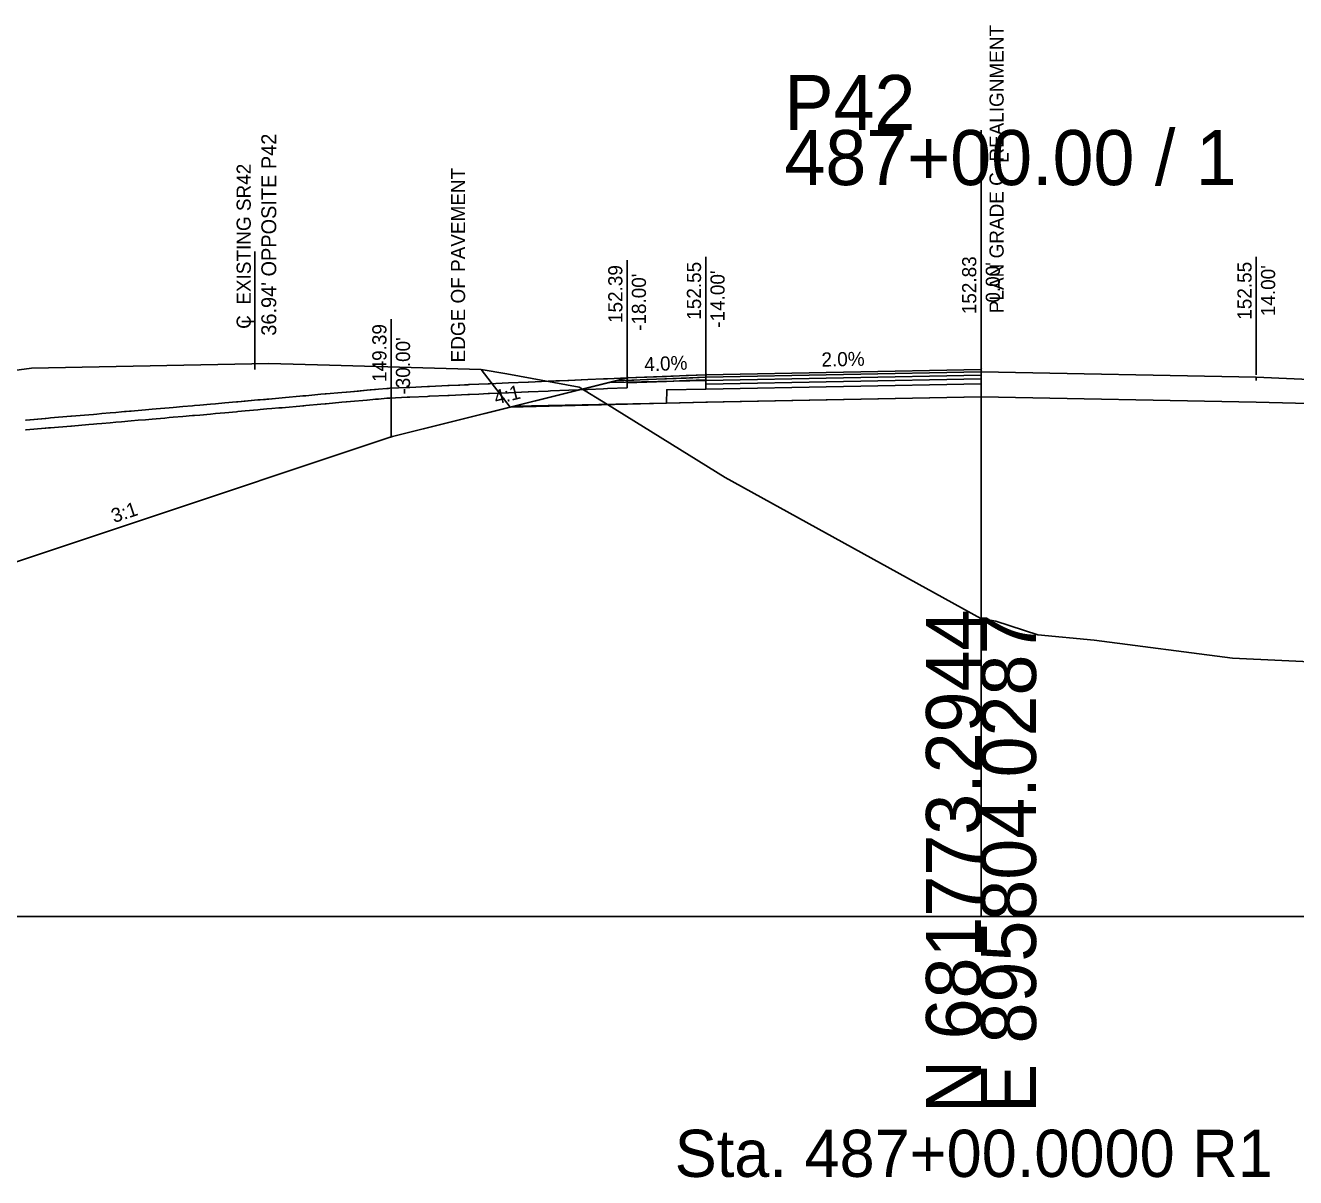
# Model space of a CAD drawing. Extents: x -100 to 7529, y -13 to 10775.
# Drawn here: x 3101.4 to 3166, y 5486.7 to 5545.3 of the extents above; entities that cross this region are included whole.
import ezdxf

# ---------------------------------------------------------------- set-up
doc = ezdxf.new("R2010")
doc.units = 0
for name, color, linetype in [('ASHPALT_12_5MM1', 7, 'Continuous'), ('ASPHALT_19MM1', 7, 'Continuous'), ('ASPHALT_19MM2', 7, 'Continuous'), ('ASPHALT_9_5MM1', 7, 'Continuous'), ('CONST_LV3', 7, 'Continuous'), ('CONST_PROF_LV1', 7, 'Continuous'), ('Default', 7, 'Continuous'), ('Draft_XS_Text', 7, 'Continuous'), ('DTM CONTOURS_MAJOR', 7, 'Continuous'), ('DTM_P_FINISHED_GRADE', 7, 'Continuous'), ('DTM_X_BOUNDARY', 7, 'Continuous'), ('DTM_X_GROUND', 7, 'Continuous'), ('XS_CELL', 7, 'Continuous'), ('XS_M_SHAPES_EARTHWORK', 7, 'Continuous'), ('XS_P_CRUSHED_STONE', 7, 'Continuous'), ('XS_P_DR_ASPHALT', 7, 'Continuous'), ('XS_P_DR_ASPHALT_B', 7, 'Continuous'), ('XS_P_DR_GRAVEL', 7, 'Continuous'), ('XS_P_GROUND', 7, 'Continuous'), ('XS_P_SHOULDER', 7, 'Continuous'), ('XS_P_SUBGRADE_GRANULAR', 7, 'Continuous'), ('XS_P_TX_CLEARZONE', 7, 'Continuous'), ('XS_P_TX_FS_BS', 7, 'Continuous')]:
    doc.layers.add(name, color=color, linetype=linetype)

msp = doc.modelspace()

# ---------------------------------------------------------------- linework, layer by layer
at = {"layer": 'ASHPALT_12_5MM1'}
msp.add_line((3164, 5527.257), (3164, 5527.424), dxfattribs=at)
at = {"layer": 'ASPHALT_19MM1'}
msp.add_lwpolyline([(3136, 5527.257), (3150, 5527.537), (3150, 5527.349), (3150, 5527.349), (3136, 5527.069), (3136, 5527.069), (3136, 5527.069), (3136, 5527.257), (3136, 5527.257)], dxfattribs=at)
at = {"layer": 'ASPHALT_19MM2'}
msp.add_lwpolyline([(3136, 5527.069), (3150, 5527.349), (3150, 5527.099), (3150, 5527.099), (3136, 5526.819), (3136, 5526.819), (3136, 5526.819), (3136, 5527.069), (3136, 5527.069)], dxfattribs=at)
at = {"layer": 'ASPHALT_9_5MM1'}
msp.add_lwpolyline([(3136, 5527.549), (3150, 5527.829), (3150, 5527.704), (3150, 5527.704), (3136, 5527.424), (3136, 5527.424), (3136, 5527.424), (3136, 5527.549), (3136, 5527.549)], dxfattribs=at)
at = {"layer": 'CONST_LV3'}
for points in [[(3101.397, 5525.247), (3101.435, 5525.25), (3101.438, 5525.251), (3102.44, 5525.334), (3102.575, 5525.346), (3102.665, 5525.354), (3103.714, 5525.442), (3103.747, 5525.445), (3104.63, 5525.518), (3104.853, 5525.539), (3105.026, 5525.554), (3105.29, 5525.576), (3105.7, 5525.61), (3105.992, 5525.637), (3106.278, 5525.661), (3106.445, 5525.677), (3106.945, 5525.719), (3107.13, 5525.736), (3107.507, 5525.767), (3107.843, 5525.795), (3108.267, 5525.835), (3108.713, 5525.872), (3108.917, 5525.889), (3109.402, 5525.935), (3109.897, 5525.976), (3109.991, 5525.984), (3110.263, 5526.006), (3110.807, 5526.057), (3111.062, 5526.078), (3111.066, 5526.079), (3111.546, 5526.118), (3112.14, 5526.174), (3112.209, 5526.18), (3112.527, 5526.21), (3112.886, 5526.239), (3113.215, 5526.27), (3113.339, 5526.28), (3113.6, 5526.302), (3114.288, 5526.366), (3114.453, 5526.379), (3114.63, 5526.394), (3115.36, 5526.462), (3115.513, 5526.474), (3115.553, 5526.478), (3115.66, 5526.486), (3116.431, 5526.558), (3116.639, 5526.575), (3116.692, 5526.579), (3117.499, 5526.654), (3117.713, 5526.671), (3117.724, 5526.672), (3118.138, 5526.71), (3118.338, 5526.726), (3118.756, 5526.765), (3118.776, 5526.767), (3118.935, 5526.779), (3119.787, 5526.858), (3119.829, 5526.861), (3119.864, 5526.862), (3119.938, 5526.866), (3120.819, 5526.907), (3120.873, 5526.91), (3120.942, 5526.912), (3121.848, 5526.955), (3121.908, 5526.957), (3121.948, 5526.959), (3122.877, 5527.002), (3122.936, 5527.004), (3122.955, 5527.005), (3123.425, 5527.026), (3123.487, 5527.029), (3123.958, 5527.05), (3123.963, 5527.05), (3123.979, 5527.051), (3124.94, 5527.094), (3125.001, 5527.097), (3125.971, 5527.139), (3126.963, 5527.182), (3126.988, 5527.183), (3127.984, 5527.225), (3128.381, 5527.242), (3128.989, 5527.267), (3128.995, 5527.267), (3129.998, 5527.308), (3130.791, 5527.34), (3131, 5527.349), (3132, 5527.389), (3133, 5527.429), (3134, 5527.469), (3135, 5527.509), (3136, 5527.549)], [(3120, 5524.389), (3120, 5524.389), (3126.28, 5525.958)]]:
    msp.add_lwpolyline(points, dxfattribs=at)
at = {"layer": 'Default'}
msp.add_lwpolyline([(3136, 5527.424), (3150, 5527.704), (3150, 5527.537), (3150, 5527.537), (3136, 5527.257), (3136, 5527.257), (3136, 5527.257), (3136, 5527.424), (3136, 5527.424)], dxfattribs=at)
at = {"layer": 'DTM_P_FINISHED_GRADE'}
for points in [[(3132, 5527.389), (3133, 5527.429), (3134, 5527.469), (3135, 5527.509), (3136, 5527.549)], [(3101.397, 5525.247), (3101.435, 5525.25), (3101.437, 5525.25), (3102.404, 5525.331), (3102.44, 5525.334), (3102.575, 5525.346), (3102.665, 5525.354), (3103.714, 5525.442), (3103.747, 5525.445), (3104.63, 5525.518), (3104.853, 5525.539), (3105.026, 5525.554), (3105.29, 5525.576), (3105.7, 5525.61), (3105.992, 5525.637), (3106.278, 5525.661), (3106.771, 5525.702), (3107.13, 5525.736), (3107.507, 5525.767), (3107.843, 5525.795), (3108.049, 5525.815), (3108.49, 5525.851), (3108.713, 5525.872), (3108.917, 5525.889), (3109.402, 5525.935), (3109.897, 5525.976), (3109.991, 5525.984), (3110.263, 5526.006), (3110.807, 5526.057), (3111.062, 5526.078), (3111.066, 5526.079), (3111.546, 5526.118), (3112.14, 5526.174), (3112.209, 5526.18), (3112.572, 5526.21), (3113.215, 5526.27), (3113.339, 5526.28), (3113.68, 5526.312), (3113.937, 5526.333), (3114.288, 5526.366), (3114.453, 5526.379), (3114.63, 5526.394), (3115.36, 5526.462), (3115.513, 5526.474), (3115.553, 5526.478), (3115.66, 5526.486), (3116.431, 5526.558), (3116.639, 5526.575), (3116.692, 5526.579), (3117.499, 5526.654), (3117.713, 5526.671), (3117.724, 5526.672), (3117.934, 5526.689), (3118.756, 5526.765), (3118.776, 5526.767), (3119.206, 5526.806), (3119.355, 5526.818), (3119.787, 5526.858), (3119.829, 5526.861), (3119.864, 5526.862), (3119.938, 5526.866), (3120.819, 5526.907), (3120.873, 5526.91), (3120.942, 5526.912), (3121.849, 5526.955), (3121.908, 5526.957), (3121.948, 5526.959), (3122.877, 5527.002), (3122.936, 5527.004), (3122.955, 5527.005), (3123.903, 5527.048), (3123.958, 5527.05), (3123.963, 5527.05), (3123.979, 5527.051), (3124.455, 5527.072), (3124.94, 5527.094), (3125.001, 5527.097), (3125.971, 5527.139), (3126.963, 5527.182), (3126.988, 5527.183), (3127.984, 5527.225), (3128.103, 5527.232), (3129.032, 5527.269), (3130.004, 5527.309), (3130.011, 5527.309), (3130.791, 5527.34), (3131, 5527.349), (3132, 5527.389)]]:
    msp.add_lwpolyline(points, dxfattribs=at)
at = {"layer": 'DTM_X_GROUND'}
for p, q in [((3126.052, 5525.901), (3124.572, 5527.826)), ((3136, 5527.424), (3131.405, 5527.24)), ((3136, 5527.424), (3150, 5527.704)), ((3150, 5527.704), (3164, 5527.424)), ((3164, 5527.424), (3168.595, 5527.24))]:
    msp.add_line(p, q, dxfattribs=at)
for points in [[(3000, 5512.2), (3044.132, 5513.453), (3046.486, 5513.62), (3053.808, 5513.95), (3070.909, 5514.966), (3077.153, 5518.209), (3097.118, 5527.209), (3098.789, 5527.5), (3101.713, 5527.882), (3110.312, 5528.066), (3113.777, 5528.123), (3116.864, 5528.039), (3124.572, 5527.826)], [(3126.052, 5525.901), (3131.405, 5527.24)]]:
    msp.add_lwpolyline(points, dxfattribs=at)
at = {"layer": 'XS_CELL'}
for p, q in [((3150, 5500), (3150, 5540)), ((3150, 5500), (3150, 5540)), ((3000, 5500), (3150, 5500)), ((3000, 5500), (3150, 5500)), ((3150, 5500), (3300, 5500)), ((3150, 5500), (3300, 5500))]:
    msp.add_line(p, q, dxfattribs=at)
at = {"layer": 'XS_M_SHAPES_EARTHWORK'}
for points in [[(3070.973, 5514.999), (3077.153, 5518.209), (3097.118, 5527.209), (3098.789, 5527.5), (3101.713, 5527.882), (3110.312, 5528.066), (3113.777, 5528.123), (3116.864, 5528.039), (3124.572, 5527.826), (3125.877, 5527.605), (3129.562, 5526.928), (3131.005, 5526.033), (3126.052, 5525.901), (3120, 5524.389), (3093.161, 5515.443)], [(3131.005, 5526.033), (3136.992, 5522.323), (3149.998, 5515.154), (3150, 5515.153), (3150.751, 5515.018), (3152.885, 5514.328), (3155.752, 5514.055), (3162.783, 5513.146), (3170.679, 5512.757), (3221.28, 5511.155), (3220.912, 5511.208), (3220.685, 5511.235), (3219.104, 5511.457), (3219.093, 5511.459), (3219.08, 5511.46), (3218.589, 5511.527), (3180, 5524.389), (3174.059, 5525.874), (3166, 5526.113), (3165.996, 5526.113), (3164, 5526.153), (3150, 5526.433), (3136, 5526.153), (3134, 5526.113)]]:
    msp.add_lwpolyline(points, close=True, dxfattribs=at)
at = {"layer": 'XS_P_CRUSHED_STONE'}
for points in [[(3132, 5527.389), (3132, 5527.389), (3131.106, 5527.165), (3131.106, 5527.165), (3131.106, 5527.165), (3136, 5527.257), (3136, 5527.257), (3136, 5527.549), (3132, 5527.389)], [(3134, 5526.113), (3136.078, 5526.154), (3136.078, 5526.154), (3150, 5526.433), (3150, 5526.433), (3150, 5527.099), (3136, 5526.819), (3136, 5526.819), (3134.014, 5526.792), (3134.014, 5526.792), (3134, 5526.113), (3134, 5526.113), (3134, 5526.113)]]:
    msp.add_lwpolyline(points, dxfattribs=at)
at = {"layer": 'XS_P_DR_ASPHALT'}
msp.add_lwpolyline([(3132, 5527.389), (3132, 5527.264), (3133, 5527.304), (3133, 5527.304), (3133, 5527.304), (3133, 5527.304), (3134, 5527.344), (3134, 5527.344), (3134, 5527.344), (3134, 5527.344), (3135, 5527.384), (3135, 5527.384), (3135, 5527.384), (3136, 5527.424), (3136, 5527.549), (3135, 5527.509), (3135, 5527.509), (3135, 5527.509), (3134, 5527.469), (3134, 5527.469), (3134, 5527.469), (3134, 5527.469), (3133, 5527.429), (3133, 5527.429), (3133, 5527.429), (3133, 5527.429), (3132, 5527.389)], dxfattribs=at)
at = {"layer": 'XS_P_DR_ASPHALT_B'}
msp.add_lwpolyline([(3132, 5527.264), (3132, 5527.139), (3133, 5527.179), (3133, 5527.179), (3133, 5527.179), (3133, 5527.179), (3134, 5527.219), (3134, 5527.219), (3134, 5527.219), (3134, 5527.219), (3135, 5527.259), (3135, 5527.259), (3135, 5527.259), (3136, 5527.299), (3136, 5527.424), (3135, 5527.384), (3135, 5527.384), (3135, 5527.384), (3134, 5527.344), (3134, 5527.344), (3134, 5527.344), (3134, 5527.344), (3133, 5527.304), (3133, 5527.304), (3133, 5527.304), (3133, 5527.304), (3132, 5527.264)], dxfattribs=at)
at = {"layer": 'XS_P_DR_GRAVEL'}
for points in [[(3101.435, 5525.25), (3101.437, 5525.25), (3102.404, 5525.331), (3102.44, 5525.334), (3102.575, 5525.346), (3102.665, 5525.354), (3103.714, 5525.442), (3103.747, 5525.445), (3104.63, 5525.518), (3104.853, 5525.539), (3105.026, 5525.554), (3105.29, 5525.576), (3105.7, 5525.61), (3105.992, 5525.637), (3106.278, 5525.661), (3106.771, 5525.702), (3107.13, 5525.736), (3107.507, 5525.767), (3107.843, 5525.795), (3108.049, 5525.815), (3108.49, 5525.851), (3108.713, 5525.872), (3108.917, 5525.889), (3109.402, 5525.935), (3109.897, 5525.976), (3109.991, 5525.984), (3110.263, 5526.006), (3110.807, 5526.057), (3111.062, 5526.078), (3111.066, 5526.079), (3111.546, 5526.118), (3112.14, 5526.174), (3112.209, 5526.18), (3112.572, 5526.21), (3113.215, 5526.27), (3113.339, 5526.28), (3113.68, 5526.312), (3113.937, 5526.333), (3114.288, 5526.366), (3114.453, 5526.379), (3114.63, 5526.394), (3115.36, 5526.462), (3115.513, 5526.474), (3115.553, 5526.478), (3115.66, 5526.486), (3116.431, 5526.558), (3116.639, 5526.575), (3116.692, 5526.579), (3117.499, 5526.654), (3117.713, 5526.671), (3117.724, 5526.672), (3117.934, 5526.689), (3118.756, 5526.765), (3118.776, 5526.767), (3119.206, 5526.806), (3119.355, 5526.818), (3119.787, 5526.858), (3119.829, 5526.861), (3119.864, 5526.862), (3119.938, 5526.866), (3120.819, 5526.907), (3120.873, 5526.91), (3120.942, 5526.912), (3121.849, 5526.955), (3121.908, 5526.957), (3121.948, 5526.959), (3122.877, 5527.002), (3122.936, 5527.004), (3122.955, 5527.005), (3123.903, 5527.048), (3123.958, 5527.05), (3123.963, 5527.05), (3123.979, 5527.051), (3124.455, 5527.072), (3124.94, 5527.094), (3125.001, 5527.097), (3125.971, 5527.139), (3126.963, 5527.182), (3126.988, 5527.183), (3127.984, 5527.225), (3128.103, 5527.232), (3129.032, 5527.269), (3130.004, 5527.309), (3130.011, 5527.309), (3130.791, 5527.34), (3131, 5527.349), (3131, 5527.349), (3131, 5527.349), (3131, 5527.349), (3132, 5527.389), (3132, 5527.389), (3132, 5526.889), (3132, 5526.889), (3131, 5526.849), (3131, 5526.849), (3131, 5526.849), (3131, 5526.849), (3130.791, 5526.84), (3130.011, 5526.809), (3130.004, 5526.809), (3129.032, 5526.769), (3128.103, 5526.732), (3127.984, 5526.725), (3126.988, 5526.683), (3126.963, 5526.682), (3125.971, 5526.639), (3125.001, 5526.597), (3124.94, 5526.594), (3124.455, 5526.572), (3123.979, 5526.551), (3123.963, 5526.55), (3123.958, 5526.55), (3123.903, 5526.548), (3122.955, 5526.505), (3122.936, 5526.504), (3122.877, 5526.502), (3121.948, 5526.459), (3121.908, 5526.457), (3121.849, 5526.455), (3120.942, 5526.412), (3120.873, 5526.41), (3120.819, 5526.407), (3119.938, 5526.366), (3119.864, 5526.362), (3119.829, 5526.361), (3119.787, 5526.358), (3119.355, 5526.318), (3119.206, 5526.306), (3118.776, 5526.267), (3118.756, 5526.265), (3117.934, 5526.189), (3117.724, 5526.172), (3117.713, 5526.171), (3117.499, 5526.154), (3116.692, 5526.079), (3116.639, 5526.075), (3116.431, 5526.058), (3115.66, 5525.986), (3115.553, 5525.978), (3115.513, 5525.974), (3115.36, 5525.962), (3114.63, 5525.894), (3114.453, 5525.879), (3114.288, 5525.866), (3113.937, 5525.833), (3113.68, 5525.812), (3113.339, 5525.78), (3113.215, 5525.77), (3112.572, 5525.71), (3112.209, 5525.68), (3112.14, 5525.674), (3111.546, 5525.618), (3111.066, 5525.579), (3111.062, 5525.578), (3110.807, 5525.557), (3110.263, 5525.506), (3109.991, 5525.484), (3109.897, 5525.476), (3109.402, 5525.435), (3108.917, 5525.389), (3108.713, 5525.372), (3108.49, 5525.351), (3108.049, 5525.315), (3107.843, 5525.295), (3107.507, 5525.267), (3107.13, 5525.236), (3106.771, 5525.202), (3106.278, 5525.161), (3105.992, 5525.137), (3105.7, 5525.11), (3105.29, 5525.076), (3105.026, 5525.054), (3104.853, 5525.039), (3104.63, 5525.018), (3103.747, 5524.945), (3103.714, 5524.942), (3102.665, 5524.854), (3102.575, 5524.846), (3102.44, 5524.834), (3102.404, 5524.831), (3101.437, 5524.75), (3101.435, 5524.75), (3101.397, 5524.747)], [(3136, 5526.819), (3136, 5527.257), (3131.106, 5527.165), (3131.106, 5527.165), (3126.052, 5525.901), (3126.052, 5525.901), (3126.052, 5525.901), (3134, 5526.113), (3134, 5526.113), (3134.014, 5526.792), (3134.014, 5526.792), (3136, 5526.819), (3136, 5526.819)], [(3101.397, 5525.247), (3101.435, 5525.25)]]:
    msp.add_lwpolyline(points, dxfattribs=at)
at = {"layer": 'XS_P_GROUND'}
msp.add_lwpolyline([(3093.161, 5515.443), (3120, 5524.389), (3120, 5524.389), (3120, 5524.389), (3132, 5527.389)], dxfattribs=at)
at = {"layer": 'XS_P_SHOULDER'}
msp.add_lwpolyline([(3136, 5527.549), (3132, 5527.389)], dxfattribs=at)
at = {"layer": 'XS_P_SUBGRADE_GRANULAR'}
for points in [[(3126.28, 5525.958), (3126.28, 5525.958), (3134, 5526.113), (3134, 5526.113), (3136, 5526.153)], [(3136, 5526.153), (3136, 5526.153), (3150, 5526.433)]]:
    msp.add_lwpolyline(points, dxfattribs=at)
at = {"layer": 'XS_P_TX_CLEARZONE'}
for p, q in [((3113.06, 5527.829), (3113.06, 5533.829)), ((3132, 5527.389), (3132, 5533.389)), ((3132, 5527.389), (3132, 5533.389)), ((3132, 5527.389), (3132, 5533.389)), ((3136, 5527.549), (3136, 5533.549)), ((3136, 5527.549), (3136, 5533.549)), ((3136, 5527.549), (3136, 5533.549)), ((3150, 5527.829), (3150, 5533.829)), ((3150, 5527.829), (3150, 5533.829)), ((3150, 5527.829), (3150, 5533.829)), ((3150, 5527.829), (3150, 5533.829)), ((3150, 5527.829), (3150, 5533.829)), ((3164, 5527.549), (3164, 5533.549)), ((3164, 5527.549), (3164, 5533.549)), ((3120, 5524.389), (3120, 5530.389)), ((3120, 5524.389), (3120, 5530.389))]:
    msp.add_line(p, q, dxfattribs=at)

# ---------------------------------------------------------------- texts
at = {"layer": 'CONST_PROF_LV1'}
msp.add_text('X', height=0.12, dxfattribs=at).set_placement((3119.961, 5524.329))
at = {"layer": 'Default'}
msp.add_text('X', height=0.12, dxfattribs=at).set_placement((3119.961, 5524.329))
at = {"layer": 'Draft_XS_Text'}
msp.add_text('Sta. 487+00.0000 R1', height=2.4, dxfattribs=at).set_placement((3134.42, 5486.75))
at = {"layer": 'DTM CONTOURS_MAJOR'}
for p in [(3135.961, 5527.489), (3149.961, 5527.769)]:
    msp.add_text('X', height=0.12, dxfattribs=at).set_placement(p)
at = {"layer": 'DTM_X_BOUNDARY'}
msp.add_text('X', height=0.12, dxfattribs=at).set_placement((3131.961, 5527.329))
at = {"layer": 'XS_CELL'}
for s, p in [('P42', (3140, 5540)), ('P42', (3140, 5540)), ('487+00.00 / 1', (3140, 5537.2)), ('487+00.00 / 1', (3140, 5537.2))]:
    msp.add_text(s, height=2.8, dxfattribs=at).set_placement(p)
for s, p in [('N 681773.2944', (3150, 5490)), ('N 681773.2944', (3150, 5490)), ('E 895804.0287', (3152.8, 5490)), ('E 895804.0287', (3152.8, 5490))]:
    msp.add_text(s, height=2.8, rotation=90, dxfattribs=at).set_placement(p)
at = {"layer": 'XS_P_TX_CLEARZONE'}
for s, height, p in [('PLAN GRADE C  REALIGNMENT', 0.72, (3151.152, 5530.687)), ("36.94' OPPOSITE P42", 0.75778, (3114.155, 5529.541)), ('L', 0.72, (3151.402, 5538.332)), ('C  EXISTING SR42', 0.72, (3112.86, 5529.887)), ('EDGE OF PAVEMENT', 0.72, (3123.76, 5528.182)), ('152.55', 0.72, (3135.76, 5530.353)), ('152.55', 0.72, (3135.76, 5530.353)), ('152.55', 0.72, (3135.76, 5530.353)), ('152.83', 0.72, (3149.76, 5530.633)), ('152.83', 0.72, (3149.76, 5530.633)), ('152.83', 0.72, (3149.76, 5530.633)), ('152.83', 0.72, (3149.76, 5530.633)), ('152.83', 0.72, (3149.76, 5530.633)), ("0.00'", 0.72, (3150.96, 5531.222)), ("0.00'", 0.72, (3150.96, 5531.222)), ('152.55', 0.72, (3163.76, 5530.353)), ('152.55', 0.72, (3163.76, 5530.353)), ('152.39', 0.72, (3131.76, 5530.187)), ('152.39', 0.72, (3131.76, 5530.187)), ('152.39', 0.72, (3131.76, 5530.187)), ("-18.00'", 0.72, (3132.96, 5529.785)), ("-18.00'", 0.72, (3132.96, 5529.785)), ("-18.00'", 0.72, (3132.96, 5529.785)), ("-14.00'", 0.72, (3136.96, 5529.945)), ("-14.00'", 0.72, (3136.96, 5529.945)), ("-14.00'", 0.72, (3136.96, 5529.945)), ("14.00'", 0.72, (3164.96, 5530.534)), ("14.00'", 0.72, (3164.96, 5530.534)), ('L', 0.72, (3113.11, 5530.138)), ('149.39', 0.72, (3119.76, 5527.187)), ('149.39', 0.72, (3119.76, 5527.187)), ("-30.00'", 0.72, (3120.96, 5526.546)), ("-30.00'", 0.72, (3120.96, 5526.546))]:
    msp.add_text(s, height=height, rotation=90, dxfattribs=at).set_placement(p)
at = {"layer": 'XS_P_TX_FS_BS'}
for s, rotation, p in [('2.0%', 1.14576, (3141.892, 5527.966)), ('4.0%', 2.29061, (3132.887, 5527.724)), ('4:1', 14.03624, (3125.333, 5526.031)), ('3:1', 18.43323, (3105.905, 5520.007))]:
    msp.add_text(s, height=0.72, rotation=rotation, dxfattribs=at).set_placement(p)

doc.saveas('drawing.dxf')
